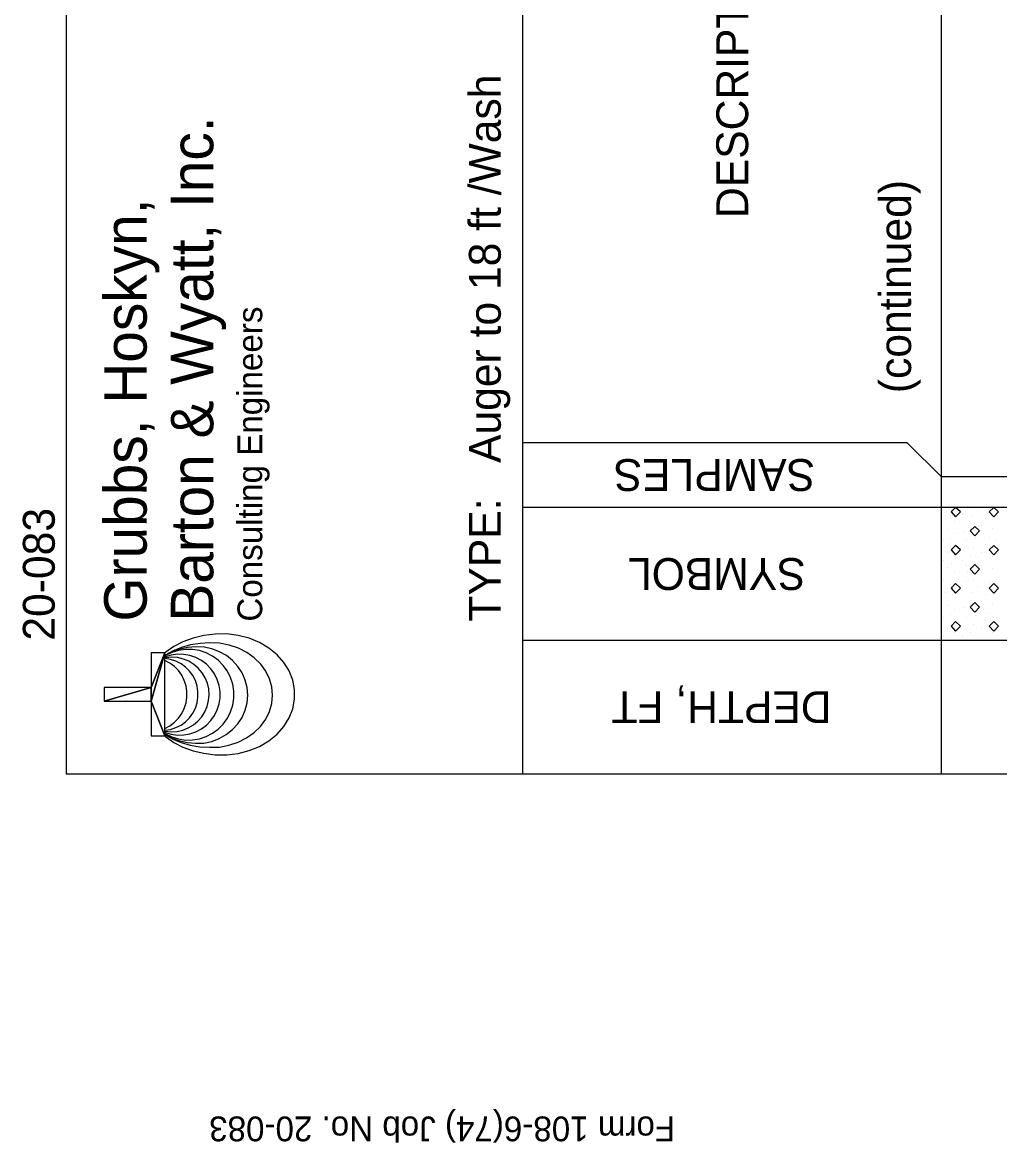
# Model space of a CAD drawing. Extents: x 1313964 to 1316843, y 2087046 to 2096619.
# Drawn here: x 1313974.69 to 1313990.3, y 2089922.27 to 2089940.17 of the extents above; entities that cross this region are included whole.
import ezdxf

# ---------------------------------------------------------------- set-up
doc = ezdxf.new("R2010")
doc.units = 0
doc.layers.add('B-Sub-Contour', color=7, linetype='Continuous')
doc.layers.add('Default', color=7, linetype='Continuous')

# ---------------------------------------------------------------- blocks, each defined once
blk = doc.blocks.new('POINT_DISPLAY')
at = {"layer": 'Default'}
blk.add_line((0, 0), (0, 0), dxfattribs=at)
blk = doc.blocks.new('DGRFC_GGHLOGO')
at = {"layer": 'Default'}
for points in [[(371581.68, 791230.32), (371581.68, 1050310.32), (295381.68, 1050310.32), (371581.68, 791230.32)], [(371581.68, 791230.32), (295381.68, 1050310.32), (295381.68, 791230.32), (371581.68, 791230.32)], [(295381.68, 791230.32), (104881.68, 791230.32), (104881.68, 715030.32), (295381.68, 791230.32)], [(295381.68, 791230.32), (104881.68, 715030.32), (562081.68, 715030.32), (295381.68, 791230.32)], [(295381.68, 791230.32), (562081.68, 715030.32), (371581.68, 791230.32), (295381.68, 791230.32)], [(562081.68, 715030.32), (562081.68, 791230.32), (371581.68, 791230.32), (562081.68, 715030.32)]]:
    blk.add_lwpolyline(points, close=True, dxfattribs=at)
for points in [[(105216.96, 715030.32), (100004.88, 709757.28), (68915.28, 666170.88), (42854.88, 615848.4), (22494.24, 560009.04), (8351.52, 500115.84), (792.48, 437662.32), (0, 374202.96), (7802.88, 311353.2), (23439.12, 250698), (46847.76, 193791.84), (77510.64, 142006.32), (114635.28, 96713.04), (157246.32, 59039.76), (204337.92, 29900.88), (254660.4, 10058.4), (306994.56, 0), (359968.8, 0), (412302.96, 10058.4), (462625.44, 29900.88), (509717.04, 59039.76), (552328.08, 96713.04), (589452.72, 142006.32), (620115.6, 193791.84), (643524.24, 250698), (659160.48, 311353.2), (666963.36, 374202.96), (666170.88, 437662.32), (658611.84, 500115.84), (644469.12, 560009.04), (624108.48, 615848.4), (598048.08, 666170.88), (566958.48, 709757.28), (561746.4, 715030.32)], [(111587.28, 715030.32), (108691.68, 711311.76), (85770.72, 670895.28), (67177.92, 625266.72), (53400.96, 575584.32), (44744.64, 523097.76), (41422.32, 469087.2), (42702.48, 414924.24), (52760.88, 362010.96), (69738.24, 311597.04), (93238.32, 264993.12), (122651.52, 223387.92), (157246.32, 187756.8), (196169.28, 159075.12), (238414.56, 137982.96), (282976.32, 125089.92), (328665.84, 120639.84), (374385.84, 124815.6), (419008.56, 137464.8), (461345.28, 158282.64), (500390.16, 186720.48), (535137.36, 222138.24), (564733.44, 263591.04), (588416.4, 310042.56), (605637.6, 360334.56), (615909.36, 413217.36), (618195.36, 467349.84), (615055.92, 521360.4), (606582.48, 573938.4), (592927.44, 623742.72), (574487.04, 669523.68), (551718.48, 710123.04), (547908.48, 715030.32)], [(113477.04, 715030.32), (111434.88, 712226.16), (91531.44, 674613.84), (76748.64, 633618.24), (67421.76, 590275.68), (63825.12, 545683.44), (65227.2, 500969.28), (74462.64, 457260.96), (90098.88, 415625.28), (111770.16, 377098.56), (138927.84, 342717.12), (170870.88, 313273.44), (206837.28, 289560), (245882.16, 272155.92), (287030.16, 261457.44), (329031.6, 257799.84), (371520.72, 261244.08), (412729.68, 271698.72), (451866, 288889.44), (487923.84, 312420), (520019.28, 341680.8), (547329.36, 375940.32), (569183.52, 414314.64), (585033.12, 455889.36), (594451.44, 499567.2), (596463.12, 544250.88), (593049.36, 588873.6), (583905.36, 632246.64), (569305.44, 673333.68), (549554.4, 711067.92), (546658.8, 715030.32)], [(117957.6, 715030.32), (116220.24, 712561.44), (98968.56, 677509.44), (87386.16, 640201.92), (81747.36, 601522.8), (82174.08, 562477.92), (88696.8, 523951.2), (101071.68, 486887.52), (119085.36, 452231.76), (142250.16, 420776.4), (170047.92, 393283.44), (201747.12, 370453.92), (236616.24, 352836.48), (273801.84, 340857.84), (312389.52, 334792.32), (351464.88, 334792.32), (390052.56, 340857.84), (427238.16, 352836.48), (462107.28, 370453.92), (493806.48, 393283.44), (521573.76, 420776.4), (544769.04, 452231.76), (562752.24, 486887.52), (575157.6, 523951.2), (581649.84, 562477.92), (582076.56, 601522.8), (576437.76, 640201.92), (564855.36, 677509.44), (547634.16, 712561.44), (545896.8, 715030.32)], [(124632.72, 715030.32), (123809.76, 713353.92), (113934.24, 680252.64), (109301.28, 646023.6), (110002.32, 611459.28), (116006.88, 577443.6), (127223.52, 544769.04), (143316.96, 514228.08), (163982.4, 486521.76), (188640.72, 462351.12), (216743.28, 442264.8), (247619.52, 426780.96), (280507.44, 416234.88), (314645.04, 410900.88), (349209.36, 410900.88), (383316.48, 416234.88), (416234.88, 426780.96), (447080.64, 442264.8), (475213.68, 462351.12), (499872, 486521.76), (520506.96, 514228.08), (536630.88, 544769.04), (547847.52, 577443.6), (553852.08, 611459.28), (554553.12, 646023.6), (549920.16, 680252.64), (540014.16, 713353.92), (539221.68, 715030.32)], [(130972.56, 715030.32), (130454.4, 713079.6), (127284.48, 680740.32), (129235.2, 648309.6), (136306.56, 616579.92), (148254.72, 586343.76), (164805.36, 558393.6), (185562.24, 533400), (210007.2, 511972.56), (237530.64, 494659.92), (267401.04, 481919.28), (298917.36, 474024.96), (331317.6, 471190.32), (363717.84, 473506.8), (395356.08, 480882.96), (425470.32, 493166.4), (453237.6, 510021.84), (478017.84, 531053.04), (499170.96, 555711.36), (516178.8, 583417.68), (528614.64, 613440.48), (536173.68, 645048.24), (538642.56, 677448.48), (535990.8, 709818.24), (534710.64, 715030.32)], [(135483.6, 715030.32), (135483.6, 714420.72), (140482.32, 683727.36), (150174.96, 654192.24), (164378.64, 626546.88), (182727.6, 601431.36), (204764.64, 579485.76), (229941.12, 561258.72), (257647.44, 547176.96), (287243.52, 537606.24), (317936.88, 532759.92), (349026.48, 532759.92), (379719.84, 537606.24), (409315.92, 547176.96), (437022.24, 561258.72), (462198.72, 579485.76), (484235.76, 601431.36), (502584.72, 626546.88), (516788.4, 654192.24), (526481.04, 683727.36), (531479.76, 714420.72), (531479.76, 715030.32)], [(146151.6, 715030.32), (160690.56, 687811.68), (179679.6, 662574.24), (202326.24, 640567.68), (228112.32, 622279.68), (256367.28, 608167.44), (286481.52, 598566.24), (317693.04, 593719.92), (349270.32, 593719.92), (380481.84, 598566.24), (410596.08, 608167.44), (438851.04, 622279.68), (464637.12, 640567.68), (487283.76, 662574.24), (506272.8, 687811.68), (520811.76, 715030.32)]]:
    blk.add_lwpolyline(points, dxfattribs=at)

msp = doc.modelspace()

# ---------------------------------------------------------------- linework, layer by layer
at = {"layer": 'B-Sub-Contour'}
for points in [[(1314036.804, 2089928.164), (1314036.804, 2089971.035), (1313975.385, 2089971.035), (1313975.385, 2089928.164), (1314036.804, 2089928.164)], [(1313982.683, 2089928.164), (1313982.683, 2089971.035)], [(1313989.372, 2089928.164), (1313989.372, 2089971.035)], [(1313988.824, 2089933.454), (1313982.683, 2089933.454)], [(1313989.372, 2089932.907), (1313988.824, 2089933.454)], [(1314034.372, 2089932.907), (1313989.372, 2089932.907)], [(1314034.372, 2089932.421), (1313982.683, 2089932.421)], [(1314034.372, 2089930.292), (1313982.683, 2089930.292)], [(1313989.372, 2089930.049), (1313989.372, 2089930.292)], [(1313989.372, 2089930.049), (1313989.372, 2089930.292)], [(1313989.372, 2089928.164), (1313989.372, 2089928.407)], [(1313989.372, 2089928.164), (1313989.372, 2089928.407)]]:
    msp.add_lwpolyline(points, dxfattribs=at)
for points in [[(1313989.597, 2089932.421), (1313989.524, 2089932.348), (1313989.597, 2089932.269), (1313989.676, 2089932.348)], [(1313990.205, 2089932.421), (1313990.132, 2089932.348), (1313990.205, 2089932.269), (1313990.284, 2089932.348)], [(1313989.901, 2089932.117), (1313989.828, 2089932.044), (1313989.901, 2089931.965), (1313989.98, 2089932.044)], [(1313989.597, 2089931.813), (1313989.524, 2089931.74), (1313989.597, 2089931.661), (1313989.676, 2089931.74)], [(1313990.205, 2089931.813), (1313990.132, 2089931.74), (1313990.205, 2089931.661), (1313990.284, 2089931.74)], [(1313989.901, 2089931.508), (1313989.828, 2089931.436), (1313989.901, 2089931.356), (1313989.98, 2089931.436)], [(1313989.597, 2089931.204), (1313989.524, 2089931.131), (1313989.597, 2089931.052), (1313989.676, 2089931.131)], [(1313990.205, 2089931.204), (1313990.132, 2089931.131), (1313990.205, 2089931.052), (1313990.284, 2089931.131)], [(1313989.901, 2089930.9), (1313989.828, 2089930.827), (1313989.901, 2089930.748), (1313989.98, 2089930.827)], [(1313989.597, 2089930.596), (1313989.524, 2089930.523), (1313989.597, 2089930.444), (1313989.676, 2089930.523)], [(1313990.205, 2089930.596), (1313990.132, 2089930.523), (1313990.205, 2089930.444), (1313990.284, 2089930.523)]]:
    msp.add_lwpolyline(points, close=True, dxfattribs=at)

# ---------------------------------------------------------------- block references
at = {"layer": 'B-Sub-Contour', "rotation": 90}
for name, p, xscale, yscale in [('POINT_DISPLAY', (1313989.524, 2089932.37), 0.019951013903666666, 0.019951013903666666), ('POINT_DISPLAY', (1313989.949, 2089932.37), 0.019951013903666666, 0.019951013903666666), ('POINT_DISPLAY', (1313989.433, 2089932.285), 0.019951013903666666, 0.019951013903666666), ('POINT_DISPLAY', (1313989.585, 2089932.188), 0.019951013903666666, 0.019951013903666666), ('POINT_DISPLAY', (1313989.706, 2089932.31), 0.019951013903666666, 0.019951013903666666), ('POINT_DISPLAY', (1313989.861, 2089932.282), 0.019951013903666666, 0.019951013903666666), ('POINT_DISPLAY', (1313990.071, 2089932.249), 0.019951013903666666, 0.019951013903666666), ('POINT_DISPLAY', (1313990.193, 2089932.31), 0.019951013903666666, 0.019951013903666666), ('POINT_DISPLAY', (1313989.463, 2089932.066), 0.019951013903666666, 0.019951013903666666), ('POINT_DISPLAY', (1313989.585, 2089932.006), 0.019951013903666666, 0.019951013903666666), ('POINT_DISPLAY', (1313989.723, 2089932.036), 0.019951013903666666, 0.019951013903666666), ('POINT_DISPLAY', (1313989.828, 2089932.066), 0.019951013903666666, 0.019951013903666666), ('POINT_DISPLAY', (1313990.01, 2089932.127), 0.019951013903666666, 0.019951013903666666), ('POINT_DISPLAY', (1313990.035, 2089932.011), 0.019951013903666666, 0.019951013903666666), ('POINT_DISPLAY', (1313990.193, 2089932.089), 0.019951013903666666, 0.019951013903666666), ('POINT_DISPLAY', (1313989.402, 2089931.884), 0.019951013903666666, 0.019951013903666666), ('POINT_DISPLAY', (1313989.518, 2089931.926), 0.019951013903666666, 0.019951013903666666), ('POINT_DISPLAY', (1313989.767, 2089931.884), 0.019951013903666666, 0.019951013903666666), ('POINT_DISPLAY', (1313989.908, 2089931.918), 0.019951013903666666, 0.019951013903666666), ('POINT_DISPLAY', (1313990.071, 2089931.823), 0.019951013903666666, 0.019951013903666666), ('POINT_DISPLAY', (1313990.132, 2089931.945), 0.019951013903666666, 0.019951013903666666), ('POINT_DISPLAY', (1313990.253, 2089931.884), 0.019951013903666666, 0.019951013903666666), ('POINT_DISPLAY', (1313989.463, 2089931.702), 0.019951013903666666, 0.019951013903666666), ('POINT_DISPLAY', (1313989.585, 2089931.641), 0.019951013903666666, 0.019951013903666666), ('POINT_DISPLAY', (1313989.645, 2089931.762), 0.019951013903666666, 0.019951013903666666), ('POINT_DISPLAY', (1313989.828, 2089931.641), 0.019951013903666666, 0.019951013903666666), ('POINT_DISPLAY', (1313989.889, 2089931.762), 0.019951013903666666, 0.019951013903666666), ('POINT_DISPLAY', (1313990.01, 2089931.702), 0.019951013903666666, 0.019951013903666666), ('POINT_DISPLAY', (1313990.193, 2089931.641), 0.019951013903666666, 0.019951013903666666), ('POINT_DISPLAY', (1313989.402, 2089931.58), 0.019951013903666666, 0.019951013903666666), ('POINT_DISPLAY', (1313989.463, 2089931.458), 0.019951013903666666, 0.019951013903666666), ('POINT_DISPLAY', (1313989.524, 2089931.519), 0.019951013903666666, 0.019951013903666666), ('POINT_DISPLAY', (1313989.706, 2089931.58), 0.019951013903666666, 0.019951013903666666), ('POINT_DISPLAY', (1313989.767, 2089931.498), 0.019951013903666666, 0.019951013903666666), ('POINT_DISPLAY', (1313989.889, 2089931.458), 0.019951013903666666, 0.019951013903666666), ('POINT_DISPLAY', (1313989.949, 2089931.519), 0.019951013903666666, 0.019951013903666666), ('POINT_DISPLAY', (1313990.179, 2089931.441), 0.019951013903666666, 0.019951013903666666), ('POINT_DISPLAY', (1313989.402, 2089931.276), 0.019951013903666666, 0.019951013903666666), ('POINT_DISPLAY', (1313989.585, 2089931.398), 0.019951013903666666, 0.019951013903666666), ('POINT_DISPLAY', (1313989.645, 2089931.276), 0.019951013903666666, 0.019951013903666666), ('POINT_DISPLAY', (1313989.784, 2089931.378), 0.019951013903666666, 0.019951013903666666), ('POINT_DISPLAY', (1313989.889, 2089931.276), 0.019951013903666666, 0.019951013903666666), ('POINT_DISPLAY', (1313990.01, 2089931.398), 0.019951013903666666, 0.019951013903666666), ('POINT_DISPLAY', (1313990.253, 2089931.276), 0.019951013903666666, 0.019951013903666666), ('POINT_DISPLAY', (1313989.433, 2089931.069), 0.019951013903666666, 0.019951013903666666), ('POINT_DISPLAY', (1313989.524, 2089931.154), 0.019951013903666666, 0.019951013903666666), ('POINT_DISPLAY', (1313989.706, 2089931.093), 0.019951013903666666, 0.019951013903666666), ('POINT_DISPLAY', (1313989.775, 2089931.231), 0.019951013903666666, 0.019951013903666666), ('POINT_DISPLAY', (1313989.861, 2089931.066), 0.019951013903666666, 0.019951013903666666), ('POINT_DISPLAY', (1313989.949, 2089931.154), 0.019951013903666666, 0.019951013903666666), ('POINT_DISPLAY', (1313990.132, 2089931.215), 0.019951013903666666, 0.019951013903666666), ('POINT_DISPLAY', (1313990.193, 2089931.093), 0.019951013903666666, 0.019951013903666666), ('POINT_DISPLAY', (1313989.585, 2089930.972), 0.019951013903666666, 0.019951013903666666), ('POINT_DISPLAY', (1313990.01, 2089930.911), 0.019951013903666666, 0.019951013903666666), ('POINT_DISPLAY', (1313990.071, 2089931.033), 0.019951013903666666, 0.019951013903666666), ('POINT_DISPLAY', (1313989.463, 2089930.85), 0.019951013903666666, 0.019951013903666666), ('POINT_DISPLAY', (1313989.518, 2089930.71), 0.019951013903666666, 0.019951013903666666), ('POINT_DISPLAY', (1313989.585, 2089930.789), 0.019951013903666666, 0.019951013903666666), ('POINT_DISPLAY', (1313989.723, 2089930.82), 0.019951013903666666, 0.019951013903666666), ('POINT_DISPLAY', (1313989.828, 2089930.85), 0.019951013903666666, 0.019951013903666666), ('POINT_DISPLAY', (1313990.035, 2089930.795), 0.019951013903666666, 0.019951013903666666), ('POINT_DISPLAY', (1313990.132, 2089930.729), 0.019951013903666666, 0.019951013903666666), ('POINT_DISPLAY', (1313990.193, 2089930.873), 0.019951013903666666, 0.019951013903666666), ('POINT_DISPLAY', (1313989.402, 2089930.668), 0.019951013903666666, 0.019951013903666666), ('POINT_DISPLAY', (1313989.645, 2089930.546), 0.019951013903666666, 0.019951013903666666), ('POINT_DISPLAY', (1313989.767, 2089930.668), 0.019951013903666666, 0.019951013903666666), ('POINT_DISPLAY', (1313989.889, 2089930.546), 0.019951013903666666, 0.019951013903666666), ('POINT_DISPLAY', (1313989.908, 2089930.701), 0.019951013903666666, 0.019951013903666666), ('POINT_DISPLAY', (1313990.071, 2089930.607), 0.019951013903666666, 0.019951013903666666), ('POINT_DISPLAY', (1313990.253, 2089930.668), 0.019951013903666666, 0.019951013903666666), ('DGRFC_GGHLOGO', (1313979.034, 2089928.468), 2.894891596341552e-06, 2.894891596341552e-06), ('POINT_DISPLAY', (1313989.402, 2089930.364), 0.019951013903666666, 0.019951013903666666), ('POINT_DISPLAY', (1313989.463, 2089930.485), 0.019951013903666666, 0.019951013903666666), ('POINT_DISPLAY', (1313989.585, 2089930.425), 0.019951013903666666, 0.019951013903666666), ('POINT_DISPLAY', (1313989.706, 2089930.364), 0.019951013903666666, 0.019951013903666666), ('POINT_DISPLAY', (1313989.828, 2089930.425), 0.019951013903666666, 0.019951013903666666), ('POINT_DISPLAY', (1313990.01, 2089930.485), 0.019951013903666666, 0.019951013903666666), ('POINT_DISPLAY', (1313990.193, 2089930.425), 0.019951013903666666, 0.019951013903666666), ('POINT_DISPLAY', (1313989.524, 2089930.303), 0.019951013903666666, 0.019951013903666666), ('POINT_DISPLAY', (1313989.949, 2089930.303), 0.019951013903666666, 0.019951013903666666)]:
    msp.add_blockref(name, p, dxfattribs=dict(at, xscale=xscale, yscale=yscale))

# ---------------------------------------------------------------- texts
at = {"layer": 'B-Sub-Contour'}
for s, height, rotation, p in [('DESCRIPTION OF MATERIAL', 0.50899, 90, (1313986.282, 2089937.043)), ('TYPE:   Auger to 18 ft /Wash', 0.50899, 90, (1313982.329, 2089930.596)), ('Barton & Wyatt, Inc.', 0.67865, 90, (1313977.736, 2089930.596)), ('(continued)', 0.50899, 90, (1313988.885, 2089934.245)), ('Grubbs, Hoskyn,', 0.67865, 90, (1313976.672, 2089930.596)), ('Consulting Engineers', 0.39588, 90, (1313978.518, 2089930.596)), ('SAMPLES', 0.509, 180, (1313987.35, 2089933.192)), ('20-083', 0.509, 90, (1313975.203, 2089930.292)), ('SYMBOL', 0.509, 180, (1313987.199, 2089931.611)), ('DEPTH, FT', 0.509, 180, (1313987.615, 2089929.483)), ('Form 108-6(74) Job No. 20-083', 0.39588, 180, (1313985.115, 2089922.691))]:
    msp.add_text(s, height=height, rotation=rotation, dxfattribs=at).set_placement(p)

doc.saveas('drawing.dxf')
